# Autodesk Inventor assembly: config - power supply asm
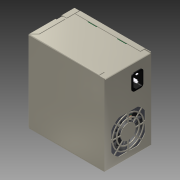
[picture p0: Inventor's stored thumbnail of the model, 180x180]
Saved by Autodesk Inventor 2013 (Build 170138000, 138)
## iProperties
Company: Autodesk Inc.
Created: 2005-12
Part Number: config - power supply asm
Document SubType Name: Assembly
Designer: Autodesk Inc.
Stock Number: config - power supply asm
Mass: 158.696 g
Surface Area: 2470.38 cm^2
Volume: 158.696 cm^3
Density: 1 g/cm^3
Title: PC Demo
Author: Autodesk Inc.
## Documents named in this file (6)
- Z:\_DATEN\Personal Computer\Power Supply\Power Supply.iam
- Z:\_DATEN\Personal Computer\Power Supply\Back Casing.ipt
- Z:\_DATEN\Personal Computer\Power Supply\Top Casing.ipt
- Z:\_DATEN\Personal Computer\Power Supply\Power Socket.ipt
- Z:\_DATEN\Personal Computer\Power Supply\Fan.ipt
- Z:\_DATEN\Personal Computer\Power Supply\Power Supply PCB.ipt
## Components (5 placed, 5 different names)
1. Back Casing:1 — Mate:1, Mate:2, Mate:3, Flush:1, Insert:1, Angle:1, Mate:4, Mate:5, Mate:6
2. Power Socket:1 — Mate:2, Mate:3, Flush:1
3. Top Casing:1 — Mate:4, Mate:5, Mate:6, Mate:7, Mate:8, Mate:9
4. Fan:1 — Insert:1, Angle:1
5. Power Supply PCB:1 — Mate:7, Mate:8, Mate:9
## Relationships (12: Mate 9, Flush 1, Insert 1, Angle 1)
- Mate:1: Back Casing:1
- Mate:2: Back Casing:1 ↔ Power Socket:1
- Mate:3: Back Casing:1 ↔ Power Socket:1
- Flush:1: Back Casing:1 ↔ Power Socket:1
- Insert:1: Back Casing:1 ↔ Fan:1
- Angle:1: Back Casing:1 ↔ Fan:1
- Mate:4: Back Casing:1 ↔ Top Casing:1
- Mate:5: Back Casing:1 ↔ Top Casing:1
- Mate:6: Back Casing:1 ↔ Top Casing:1
- Mate:7: Top Casing:1 ↔ Power Supply PCB:1
- Mate:8: Top Casing:1 ↔ Power Supply PCB:1
- Mate:9: Top Casing:1 ↔ Power Supply PCB:1
